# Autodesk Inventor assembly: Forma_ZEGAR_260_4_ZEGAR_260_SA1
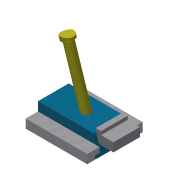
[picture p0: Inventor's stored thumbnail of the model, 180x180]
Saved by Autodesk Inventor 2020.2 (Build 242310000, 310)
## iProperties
Created: 2015-01
Part Number: Forma_ZEGAR_260_4_ZEGAR_260_SA1
Document SubType Name: Assembly
Designer: F.Stasiak
Catalog Web Link: www.expertbooks.pl
Manager: www.cadconsulting.pl
Company: Fabian Stasiak CAD Consulting
Author: F.Stasiak
Subject: Zbiór ćwiczeń. Autodesk Inventor 2020. Kurs Professional
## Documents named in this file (6)
- C:\2020_Kurs_Professional\R6 Formy\Komponenty\Suwaki\GENERIC_Zwykła blokada pojedyncza 1 1\Forma_ZEGAR_260_4_ZEGAR_260_SA1.iam
- C:\2020_Kurs_Professional\R6 Formy\Komponenty\Suwaki\GENERIC_Zwykła blokada pojedyncza 1 1\Forma_ZEGAR_260_4_ZEGAR_260_SA1_Generic1 Angle Pin.ipt
- C:\2020_Kurs_Professional\R6 Formy\Komponenty\Suwaki\GENERIC_Zwykła blokada pojedyncza 1 1\Forma_ZEGAR_260_4_ZEGAR_260_SA1_Generic1 Locking Heel.ipt
- C:\2020_Kurs_Professional\R6 Formy\Komponenty\Suwaki\GENERIC_Zwykła blokada pojedyncza 1 1\Forma_ZEGAR_260_4_ZEGAR_260_SA1_Generic1 Guide Strip.ipt
- C:\2020_Kurs_Professional\R6 Formy\Komponenty\Suwaki\GENERIC_Zwykła blokada pojedyncza 1 1\Forma_ZEGAR_260_4_ZEGAR_260_SA1_Generic1 Slider.ipt
- C:\2020_Kurs_Professional\R6 Formy\Komponenty\Suwaki\GENERIC_Zwykła blokada pojedyncza 1 1\Forma_ZEGAR_260_4_ZEGAR_260_SA1_Generic1 Guide Strip_1.ipt
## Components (5 placed, 5 different names)
1. Forma_ZEGAR_260_4_ZEGAR_260_SA1_Generic1 Angle Pin:1 — Równoległy:67, Zestawiający:13
2. Forma_ZEGAR_260_4_ZEGAR_260_SA1_Generic1 Locking Heel:1 — Równoległy:68, Równoległy:69, Styczny:1
3. Forma_ZEGAR_260_4_ZEGAR_260_SA1_Generic1 Guide Strip:1 — Równoległy:67, Równoległy:69, Równoległy:70, Równoległy:71, Zestawiający:14, Równoległy:74, Równoległy:75, Równoległy:76, Równoległy:77
4. Forma_ZEGAR_260_4_ZEGAR_260_SA1_Generic1 Slider:1 — Zestawiający:13, Styczny:1, Zestawiający:14, Równoległy:72, Równoległy:73, Równoległy:74
5. Forma_ZEGAR_260_4_ZEGAR_260_SA1_Generic1 Guide Strip_1:1 — Równoległy:75, Równoległy:76, Równoległy:77
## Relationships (14: Flush 11, Mate 2, Tangent 1)
- Równoległy:67 [Flush]: Forma_ZEGAR_260_4_ZEGAR_260_SA1_Generic1 Angle Pin:1 ↔ Forma_ZEGAR_260_4_ZEGAR_260_SA1_Generic1 Guide Strip:1
- Zestawiający:13 [Mate]: Forma_ZEGAR_260_4_ZEGAR_260_SA1_Generic1 Angle Pin:1 ↔ Forma_ZEGAR_260_4_ZEGAR_260_SA1_Generic1 Slider:1
- Równoległy:68 [Flush]: Forma_ZEGAR_260_4_ZEGAR_260_SA1_Generic1 Locking Heel:1
- Równoległy:69 [Flush]: Forma_ZEGAR_260_4_ZEGAR_260_SA1_Generic1 Locking Heel:1 ↔ Forma_ZEGAR_260_4_ZEGAR_260_SA1_Generic1 Guide Strip:1
- Styczny:1 [Tangent]: Forma_ZEGAR_260_4_ZEGAR_260_SA1_Generic1 Locking Heel:1 ↔ Forma_ZEGAR_260_4_ZEGAR_260_SA1_Generic1 Slider:1
- Równoległy:70 [Flush]: Forma_ZEGAR_260_4_ZEGAR_260_SA1_Generic1 Guide Strip:1
- Równoległy:71 [Flush]: Forma_ZEGAR_260_4_ZEGAR_260_SA1_Generic1 Guide Strip:1
- Zestawiający:14 [Mate]: Forma_ZEGAR_260_4_ZEGAR_260_SA1_Generic1 Guide Strip:1 ↔ Forma_ZEGAR_260_4_ZEGAR_260_SA1_Generic1 Slider:1
- Równoległy:72 [Flush]: Forma_ZEGAR_260_4_ZEGAR_260_SA1_Generic1 Slider:1
- Równoległy:73 [Flush]: Forma_ZEGAR_260_4_ZEGAR_260_SA1_Generic1 Slider:1
- Równoległy:74 [Flush]: Forma_ZEGAR_260_4_ZEGAR_260_SA1_Generic1 Guide Strip:1 ↔ Forma_ZEGAR_260_4_ZEGAR_260_SA1_Generic1 Slider:1
- Równoległy:75 [Flush]: Forma_ZEGAR_260_4_ZEGAR_260_SA1_Generic1 Guide Strip:1 ↔ Forma_ZEGAR_260_4_ZEGAR_260_SA1_Generic1 Guide Strip_1:1
- Równoległy:76 [Flush]: Forma_ZEGAR_260_4_ZEGAR_260_SA1_Generic1 Guide Strip:1 ↔ Forma_ZEGAR_260_4_ZEGAR_260_SA1_Generic1 Guide Strip_1:1
- Równoległy:77 [Flush]: Forma_ZEGAR_260_4_ZEGAR_260_SA1_Generic1 Guide Strip:1 ↔ Forma_ZEGAR_260_4_ZEGAR_260_SA1_Generic1 Guide Strip_1:1
